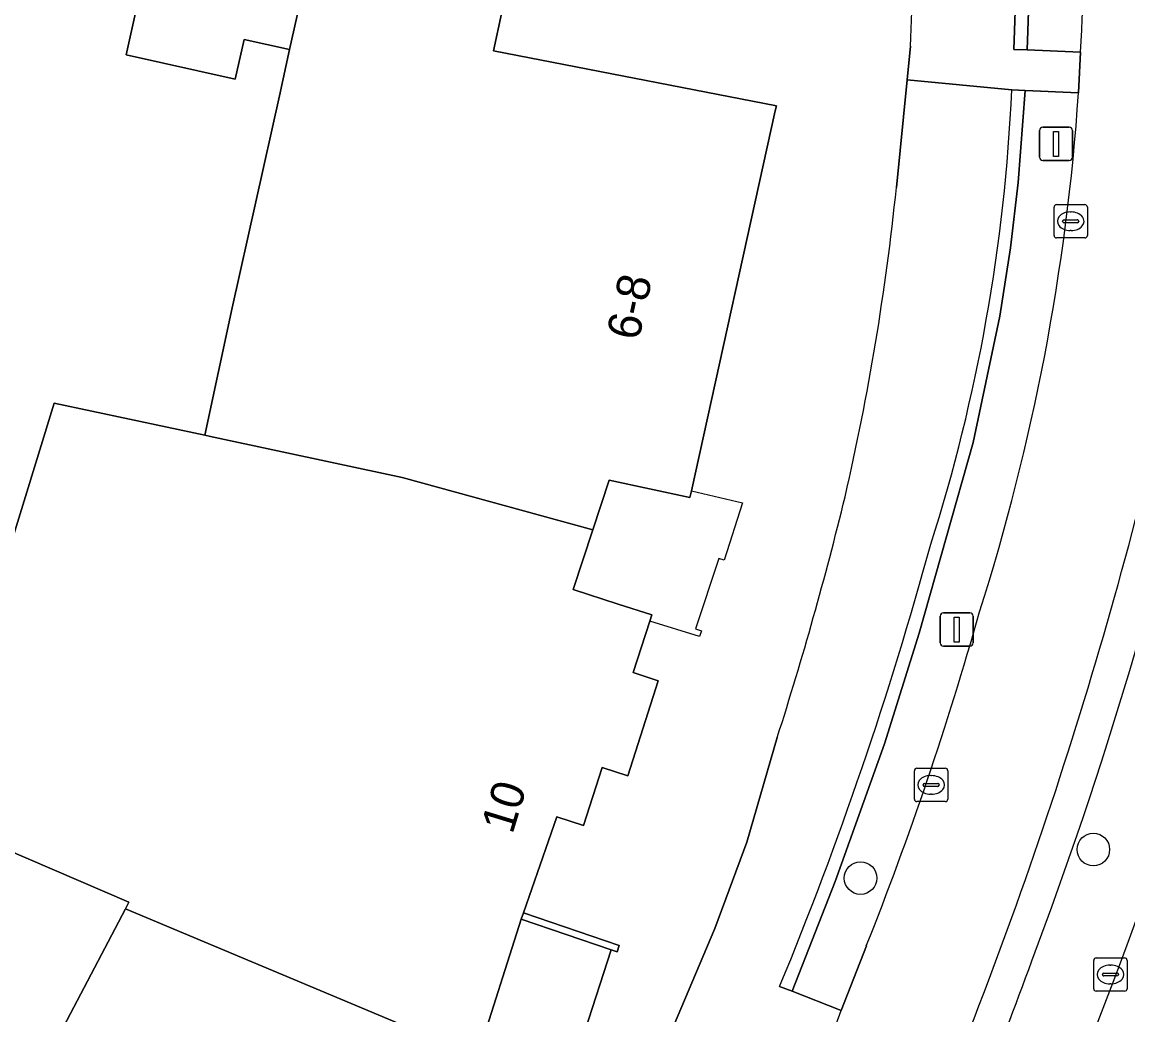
# Model space of a CAD drawing. Extents: x 161772 to 163126, y 383092 to 383917.
# Drawn here: x 161943.6 to 161976.79, y 383340.19 to 383370 of the extents above; entities that cross this region are included whole.
import ezdxf

# ---------------------------------------------------------------- set-up
doc = ezdxf.new("R2010")
doc.units = 0
for name, color, linetype in [('IMGEO_Berm_open', 7, 'Continuous'), ('IMGEO_Boom', 7, 'Continuous'), ('IMGEO_Erf', 7, 'Continuous'), ('IMGEO_Fietspad_gesloten', 7, 'Continuous'), ('IMGEO_Groenvoorziening', 7, 'Continuous'), ('IMGEO_Haag', 7, 'Continuous'), ('IMGEO_Kolk', 7, 'Continuous'), ('IMGEO_Lichtmast', 7, 'Continuous'), ('IMGEO_Muur', 7, 'Continuous'), ('IMGEO_Pand', 7, 'Continuous'), ('IMGEO_Pand_nummerreeks', 7, 'Continuous'), ('IMGEO_Parkeervlak_open', 7, 'Continuous'), ('IMGEO_Rijbaan_lokaal_open', 7, 'Continuous'), ('IMGEO_Voetpad_gesloten', 7, 'Continuous'), ('IMGEO_Voetpad_open', 7, 'Continuous')]:
    doc.layers.add(name, color=color, linetype=linetype)

msp = doc.modelspace()

# ---------------------------------------------------------------- linework, layer by layer
at = {"layer": 'IMGEO_Berm_open'}
for centre, radius, start, end in [((161843.108, 383390.109), 138.426, 336.63706, 347.34586), ((161848.959, 383388.745), 133.48, 339.41244, 347.31379), ((161824.213, 383396.839), 159.496, 336.68831, 339.8164)]:
    msp.add_arc(centre, radius, start, end, dxfattribs=at)
at = {"layer": 'IMGEO_Boom'}
for centre in [(161975.758, 383345.154), (161968.769, 383344.296)]:
    msp.add_circle(centre, 0.489, dxfattribs=at)
at = {"layer": 'IMGEO_Erf'}
for points in [[(161944.838, 383339.825), (161946.7, 383343.376), (161946.801, 383343.568), (161940.744, 383346.18), (161944.563, 383358.562), (161949.084, 383357.595), (161949.903, 383361.425), (161951.32, 383367.789), (161951.629, 383369.179), (161950.263, 383369.483), (161949.997, 383368.286), (161946.718, 383369.015), (161947.624, 383373.087)], [(161957.998, 383370.297), (161957.751, 383369.143), (161966.242, 383367.486), (161966.208, 383367.333), (161963.689, 383355.927), (161963.646, 383355.724), (161961.226, 383356.243), (161960.733, 383354.757), (161960.137, 383352.963), (161961.491, 383352.527), (161962.503, 383352.201), (161962.444, 383352.01), (161961.946, 383350.473), (161962.695, 383350.218), (161961.777, 383347.368), (161961.016, 383347.613), (161960.45, 383345.875), (161959.65, 383346.135), (161958.645, 383343.251), (161961.524, 383342.27), (161961.464, 383342.083), (161961.282, 383342.145), (161960.493, 383339.694)], [(161969.844, 383365.031), (161970.168, 383368.269), (161970.269, 383369.275)], [(161962.387, 383338.024), (161964.39, 383342.786), (161965.359, 383345.377), (161966.269, 383348.522)]]:
    msp.add_lwpolyline(points, dxfattribs=at)
for centre, radius, start, end in [((161880.607, 383372.91), 89.736, 357.67817, 3.02055), ((161894.564, 383372.742), 75.674, 347.02221, 354.15125), ((161863.824, 383381.287), 107.557, 342.26427, 346.26427)]:
    msp.add_arc(centre, radius, start, end, dxfattribs=at)
at = {"layer": 'IMGEO_Fietspad_gesloten'}
for points in [[(161975.372, 383369.103), (161975.312, 383367.874)], [(161968.943, 383342.26), (161968.185, 383340.324)]]:
    msp.add_lwpolyline(points, dxfattribs=at)
for centre, radius, start, end in [((161907.089, 383373.249), 68.409, 356.52541, 5.41022), ((161909.48, 383372.353), 65.985, 342.29827, 356.10745), ((161843.108, 383390.109), 138.426, 336.63706, 347.34586), ((161874.301, 383379.904), 101.853, 338.30974, 344.26943), ((161922.938, 383356.536), 48.064, 323.4291, 340.2872)]:
    msp.add_arc(centre, radius, start, end, dxfattribs=at)
at = {"layer": 'IMGEO_Groenvoorziening'}
for points in [[(161971.921, 383396.62), (161969.508, 383405.824), (161967.979, 383405.437), (161970.76, 383394.838), (161971.696, 383390.984), (161972.516, 383386.826), (161972.897, 383384.465), (161973.463, 383379.935), (161973.746, 383376.726), (161973.914, 383373.196), (161973.773, 383369.167), (161975.372, 383369.103)], [(161973.513, 383373.196), (161973.373, 383369.183), (161973.773, 383369.167), (161973.914, 383373.196), (161973.746, 383376.726), (161973.463, 383379.935), (161972.897, 383384.465), (161972.516, 383386.826), (161971.696, 383390.984), (161970.76, 383394.838), (161967.979, 383405.437), (161967.591, 383405.339), (161969.94, 383396.311)], [(161966.34, 383341.04), (161966.713, 383340.895), (161968.008, 383344.192), (161969.484, 383348.328), (161970.532, 383351.649), (161972.145, 383357.379), (161972.954, 383361.175), (161973.27, 383363.225), (161973.501, 383365.183), (161973.707, 383367.951), (161973.308, 383367.97)], [(161975.312, 383367.874), (161973.707, 383367.951), (161973.501, 383365.183), (161973.27, 383363.225), (161972.954, 383361.175), (161972.145, 383357.379), (161970.532, 383351.649), (161969.484, 383348.328), (161968.008, 383344.192), (161966.713, 383340.895), (161968.185, 383340.324), (161968.943, 383342.26)]]:
    msp.add_lwpolyline(points, dxfattribs=at)
for centre, radius, start, end in [((161907.089, 383373.249), 68.409, 356.52541, 5.41022), ((161920.79, 383370.284), 52.569, 342.3272, 357.4772), ((161909.48, 383372.353), 65.985, 342.29827, 356.10745), ((161861.639, 383384.222), 113.256, 337.58711, 344.69376), ((161874.301, 383379.904), 101.853, 338.30974, 344.26943)]:
    msp.add_arc(centre, radius, start, end, dxfattribs=at)
at = {"layer": 'IMGEO_Haag'}
for points in [[(161973.513, 383373.196), (161973.373, 383369.183), (161973.773, 383369.167), (161973.914, 383373.196), (161973.746, 383376.726), (161973.463, 383379.935), (161972.897, 383384.465), (161972.516, 383386.826), (161971.696, 383390.984), (161970.76, 383394.838), (161967.979, 383405.437), (161967.591, 383405.339), (161969.94, 383396.311)], [(161969.484, 383348.328), (161970.532, 383351.649), (161972.145, 383357.379), (161972.954, 383361.175), (161973.27, 383363.225), (161973.501, 383365.183), (161973.707, 383367.951), (161973.308, 383367.97)], [(161966.34, 383341.04), (161966.713, 383340.895), (161968.008, 383344.192), (161969.484, 383348.328)]]:
    msp.add_lwpolyline(points, dxfattribs=at)
for centre, radius, start, end in [((161920.79, 383370.284), 52.569, 342.3272, 357.4772), ((161861.639, 383384.222), 113.256, 337.58711, 344.69376)]:
    msp.add_arc(centre, radius, start, end, dxfattribs=at)
at = {"layer": 'IMGEO_Kolk'}
for p, q in [((161974.577, 383363.595), (161974.577, 383364.447)), ((161974.652, 383364.521), (161975.504, 383364.521)), ((161975.578, 383364.447), (161975.578, 383363.595)), ((161975.065, 383364.301), (161975.09, 383364.301)), ((161974.836, 383364.015), (161974.836, 383364.027)), ((161975.274, 383363.978), (161974.876, 383363.978)), ((161974.879, 383364.064), (161975.277, 383364.064)), ((161975.088, 383363.741), (161975.063, 383363.741)), ((161975.32, 383364.027), (161975.32, 383364.015)), ((161975.504, 383363.521), (161974.652, 383363.521)), ((161970.386, 383346.668), (161970.386, 383347.52)), ((161970.461, 383347.594), (161971.313, 383347.594)), ((161971.387, 383347.52), (161971.387, 383346.668)), ((161970.688, 383347.137), (161971.086, 383347.137)), ((161970.874, 383347.374), (161970.899, 383347.374)), ((161970.645, 383347.088), (161970.645, 383347.1)), ((161971.083, 383347.051), (161970.685, 383347.051)), ((161970.897, 383346.814), (161970.872, 383346.814)), ((161971.129, 383347.1), (161971.129, 383347.088)), ((161971.313, 383346.594), (161970.461, 383346.594)), ((161975.77, 383340.973), (161975.77, 383341.825)), ((161975.845, 383341.899), (161976.697, 383341.899)), ((161976.771, 383341.825), (161976.771, 383340.973)), ((161976.258, 383341.679), (161976.283, 383341.679)), ((161976.029, 383341.393), (161976.029, 383341.405)), ((161976.467, 383341.356), (161976.069, 383341.356)), ((161976.072, 383341.442), (161976.47, 383341.442)), ((161976.513, 383341.405), (161976.513, 383341.393)), ((161976.697, 383340.899), (161975.845, 383340.899)), ((161976.281, 383341.119), (161976.256, 383341.119))]:
    msp.add_line(p, q, dxfattribs=at)
for points in [[(161974.577, 383363.595), (161974.577, 383364.447)], [(161974.652, 383364.521), (161975.504, 383364.521)], [(161975.578, 383364.447), (161975.578, 383363.595)], [(161975.504, 383363.521), (161974.652, 383363.521)], [(161970.386, 383346.668), (161970.386, 383347.52)], [(161970.461, 383347.594), (161971.313, 383347.594)], [(161971.387, 383347.52), (161971.387, 383346.668)], [(161971.313, 383346.594), (161970.461, 383346.594)], [(161975.77, 383340.973), (161975.77, 383341.825)], [(161975.845, 383341.899), (161976.697, 383341.899)], [(161976.771, 383341.825), (161976.771, 383340.973)], [(161976.697, 383340.899), (161975.845, 383340.899)]]:
    msp.add_lwpolyline(points, dxfattribs=at)
for centre, radius, start, end in [((161974.654, 383364.445), 0.0765, 91.552, 178.448), ((161974.654, 383364.445), 0.0765, 91.552, 178.448), ((161975.502, 383364.445), 0.0765, 1.552, 88.448), ((161975.502, 383364.445), 0.0765, 1.552, 88.448), ((161974.876, 383364.024), 0.0403, 85.8775, 175.7526), ((161974.873, 383364.014), 0.0366, 178.938, 274.7102), ((161975.277, 383364.021), 0.043, 264.8664, 352.4533), ((161975.281, 383364.026), 0.0386, 1.7309, 96.639), ((161974.654, 383363.597), 0.0765, 181.552, 268.448), ((161974.654, 383363.597), 0.0765, 181.552, 268.448), ((161975.502, 383363.597), 0.0765, 271.552, 358.448), ((161975.502, 383363.597), 0.0765, 271.552, 358.448), ((161970.463, 383347.518), 0.0765, 91.552, 178.448), ((161970.463, 383347.518), 0.0765, 91.552, 178.448), ((161971.311, 383347.518), 0.0765, 1.552, 88.448), ((161971.311, 383347.518), 0.0765, 1.552, 88.448), ((161970.685, 383347.097), 0.0403, 85.8775, 175.7526), ((161971.09, 383347.099), 0.0386, 1.7309, 96.639), ((161970.682, 383347.087), 0.0366, 178.938, 274.7102), ((161971.086, 383347.094), 0.043, 264.8664, 352.4533), ((161970.463, 383346.67), 0.0765, 181.552, 268.448), ((161970.463, 383346.67), 0.0765, 181.552, 268.448), ((161971.311, 383346.67), 0.0765, 271.552, 358.448), ((161971.311, 383346.67), 0.0765, 271.552, 358.448), ((161975.847, 383341.823), 0.0765, 91.552, 178.448), ((161975.847, 383341.823), 0.0765, 91.552, 178.448), ((161976.695, 383341.823), 0.0765, 1.552, 88.448), ((161976.695, 383341.823), 0.0765, 1.552, 88.448), ((161976.069, 383341.402), 0.0403, 85.8775, 175.7526), ((161976.066, 383341.392), 0.0366, 178.938, 274.7102), ((161976.47, 383341.399), 0.043, 264.8664, 352.4533), ((161976.474, 383341.404), 0.0386, 1.7309, 96.639), ((161975.847, 383340.975), 0.0765, 181.552, 268.448), ((161975.847, 383340.975), 0.0765, 181.552, 268.448), ((161976.695, 383340.975), 0.0765, 271.552, 358.448), ((161976.695, 383340.975), 0.0765, 271.552, 358.448)]:
    msp.add_arc(centre, radius, start, end, dxfattribs=at)
for centre, major_axis, ratio, start_param, end_param in [((161975.064, 383364.021), (-0.387, 0.002), 0.722429, 4.712389, 7.853982), ((161975.089, 383364.021), (-0.39, 0.002), 0.717154, 1.570796, 4.712389), ((161970.873, 383347.094), (-0.387, 0.002), 0.722429, 4.712389, 7.853982), ((161970.898, 383347.094), (-0.39, 0.002), 0.717154, 1.570796, 4.712389), ((161976.257, 383341.399), (-0.387, 0.002), 0.722429, 4.712389, 7.853982), ((161976.282, 383341.399), (-0.39, 0.002), 0.717154, 1.570796, 4.712389)]:
    msp.add_ellipse(centre, major_axis=major_axis, ratio=ratio, start_param=start_param, end_param=end_param, dxfattribs=at)
at = {"layer": 'IMGEO_Lichtmast'}
for p, q in [((161974.143, 383365.944), (161974.143, 383366.744)), ((161974.143, 383366.744), (161974.143, 383365.944)), ((161974.243, 383366.844), (161975.033, 383366.844)), ((161975.033, 383366.844), (161974.243, 383366.844)), ((161975.133, 383366.744), (161975.133, 383365.944)), ((161975.133, 383365.944), (161975.133, 383366.744)), ((161975.033, 383365.844), (161974.243, 383365.844)), ((161974.243, 383365.844), (161975.033, 383365.844)), ((161971.161, 383351.359), (161971.161, 383352.159)), ((161971.161, 383352.159), (161971.161, 383351.359)), ((161971.261, 383352.259), (161972.051, 383352.259)), ((161972.051, 383352.259), (161971.261, 383352.259)), ((161972.151, 383352.159), (161972.151, 383351.359)), ((161972.151, 383351.359), (161972.151, 383352.159)), ((161972.051, 383351.259), (161971.261, 383351.259)), ((161971.261, 383351.259), (161972.051, 383351.259))]:
    msp.add_line(p, q, dxfattribs=at)
for points in [[(161974.563, 383366.719), (161974.713, 383366.719), (161974.713, 383365.969), (161974.563, 383365.969), (161974.563, 383366.719)], [(161971.581, 383352.134), (161971.731, 383352.134), (161971.731, 383351.384), (161971.581, 383351.384), (161971.581, 383352.134)]]:
    msp.add_lwpolyline(points, dxfattribs=at)
for centre, start, end in [((161974.243, 383366.744), 90, 180), ((161974.243, 383366.744), 90, 180), ((161975.033, 383366.744), 0, 90), ((161975.033, 383366.744), 360, 90), ((161974.243, 383365.944), 180, 270), ((161974.243, 383365.944), 180, 270), ((161975.033, 383365.944), 270, 0), ((161975.033, 383365.944), 270, 0), ((161971.261, 383352.159), 90, 180), ((161971.261, 383352.159), 90, 180), ((161972.051, 383352.159), 0, 90), ((161972.051, 383352.159), 360, 90), ((161971.261, 383351.359), 180, 270), ((161971.261, 383351.359), 180, 270), ((161972.051, 383351.359), 270, 0), ((161972.051, 383351.359), 270, 0)]:
    msp.add_arc(centre, 0.1, start, end, dxfattribs=at)
at = {"layer": 'IMGEO_Muur'}
msp.add_lwpolyline([(161963.689, 383355.927), (161965.221, 383355.568), (161964.678, 383353.844), (161964.518, 383353.896), (161963.817, 383351.777), (161963.992, 383351.723), (161963.934, 383351.548), (161962.444, 383352.01)], dxfattribs=at)
msp.add_lwpolyline([(161961.282, 383342.145), (161961.464, 383342.083), (161961.524, 383342.27), (161958.645, 383343.251), (161958.58, 383343.06)], close=True, dxfattribs=at)
at = {"layer": 'IMGEO_Pand'}
for points in [[(161952.156, 383371.547), (161952.489, 383373.044), (161951.056, 383373.363), (161947.624, 383373.087), (161946.718, 383369.015), (161949.997, 383368.286), (161950.263, 383369.483), (161951.629, 383369.179)], [(161966.208, 383367.333), (161966.242, 383367.486), (161957.751, 383369.143), (161957.998, 383370.297), (161953.109, 383371.343), (161952.156, 383371.547), (161951.629, 383369.179), (161951.32, 383367.789), (161949.903, 383361.425), (161949.084, 383357.595), (161949.25, 383357.56), (161955.008, 383356.328), (161960.733, 383354.757), (161961.226, 383356.243), (161963.646, 383355.724), (161963.689, 383355.927)], [(161962.695, 383350.218), (161961.946, 383350.473), (161962.444, 383352.01), (161962.503, 383352.201), (161961.491, 383352.527), (161960.137, 383352.963), (161960.733, 383354.757), (161955.008, 383356.328), (161949.25, 383357.56), (161949.084, 383357.595), (161944.563, 383358.562), (161940.744, 383346.18), (161946.801, 383343.568), (161946.7, 383343.376), (161957.265, 383338.941), (161958.58, 383343.06), (161958.645, 383343.251), (161959.65, 383346.135), (161960.45, 383345.875), (161961.016, 383347.613), (161961.777, 383347.368)], [(161957.265, 383338.941), (161946.7, 383343.376), (161944.838, 383339.825), (161945.895, 383339.271), (161943.966, 383335.592), (161946.478, 383334.276), (161946.289, 383333.916), (161954.063, 383329.898), (161954.362, 383330.575), (161955.048, 383330.272), (161956.459, 383333.461), (161955.781, 383333.782), (161958.069, 383338.615)]]:
    msp.add_lwpolyline(points, close=True, dxfattribs=at)
at = {"layer": 'IMGEO_Parkeervlak_open'}
for centre, radius, start, end in [((161862.08, 383384.241), 122.123, 338.69306, 349.18928), ((161848.959, 383388.745), 133.48, 339.41244, 347.31379), ((161824.213, 383396.839), 159.496, 336.68831, 339.8164)]:
    msp.add_arc(centre, radius, start, end, dxfattribs=at)
at = {"layer": 'IMGEO_Rijbaan_lokaal_open'}
for centre, radius, start, end in [((161862.08, 383384.241), 122.123, 338.69306, 349.18928), ((161825.152, 383396.521), 164.034, 336.54784, 341.7429)]:
    msp.add_arc(centre, radius, start, end, dxfattribs=at)
at = {"layer": 'IMGEO_Voetpad_gesloten'}
msp.add_lwpolyline([(161970.269, 383369.275), (161970.168, 383368.269), (161973.308, 383367.97), (161973.707, 383367.951), (161975.312, 383367.874), (161975.372, 383369.103), (161973.773, 383369.167), (161973.373, 383369.183), (161973.513, 383373.196)], dxfattribs=at)
msp.add_arc((161880.607, 383372.91), 89.736, 357.67817, 3.02055, dxfattribs=at)
at = {"layer": 'IMGEO_Voetpad_open'}
for points in [[(161973.308, 383367.97), (161970.168, 383368.269), (161969.844, 383365.031)], [(161966.269, 383348.522), (161965.359, 383345.377), (161964.39, 383342.786), (161962.387, 383338.024), (161959.895, 383332.543), (161959.195, 383331.001), (161957.936, 383328.362), (161958.095, 383328.287), (161956.227, 383324.789), (161956.346, 383324.34), (161954.519, 383321.774), (161948.264, 383313.526)], [(161968.185, 383340.324), (161966.713, 383340.895), (161966.34, 383341.04)]]:
    msp.add_lwpolyline(points, dxfattribs=at)
msp.add_lwpolyline([(161959.895, 383332.543), (161958.367, 383333.067), (161958.179, 383333.135), (161960.493, 383339.694), (161961.282, 383342.145), (161958.58, 383343.06), (161957.265, 383338.941), (161958.069, 383338.615), (161958.716, 383338.365), (161958.905, 383338.298), (161956.661, 383331.907), (161957.855, 383331.498), (161959.195, 383331.001)], close=True, dxfattribs=at)
for centre, radius, start, end in [((161920.79, 383370.284), 52.569, 342.3272, 357.4772), ((161894.564, 383372.742), 75.674, 347.02221, 354.15125), ((161863.824, 383381.287), 107.557, 342.26427, 346.26427), ((161861.639, 383384.222), 113.256, 337.58711, 344.69376), ((161825.152, 383396.521), 164.034, 336.54784, 341.7429), ((161922.938, 383356.536), 48.064, 323.4291, 340.2872)]:
    msp.add_arc(centre, radius, start, end, dxfattribs=at)

# ---------------------------------------------------------------- texts
at = {"layer": 'IMGEO_Pand_nummerreeks'}
for s, rotation, p in [('6-8', 77.8707, (161962.11, 383360.41)), ('10', 72.9776, (161958.316, 383345.588))]:
    msp.add_text(s, height=1, rotation=rotation, dxfattribs=at).set_placement(p)

doc.saveas('drawing.dxf')
